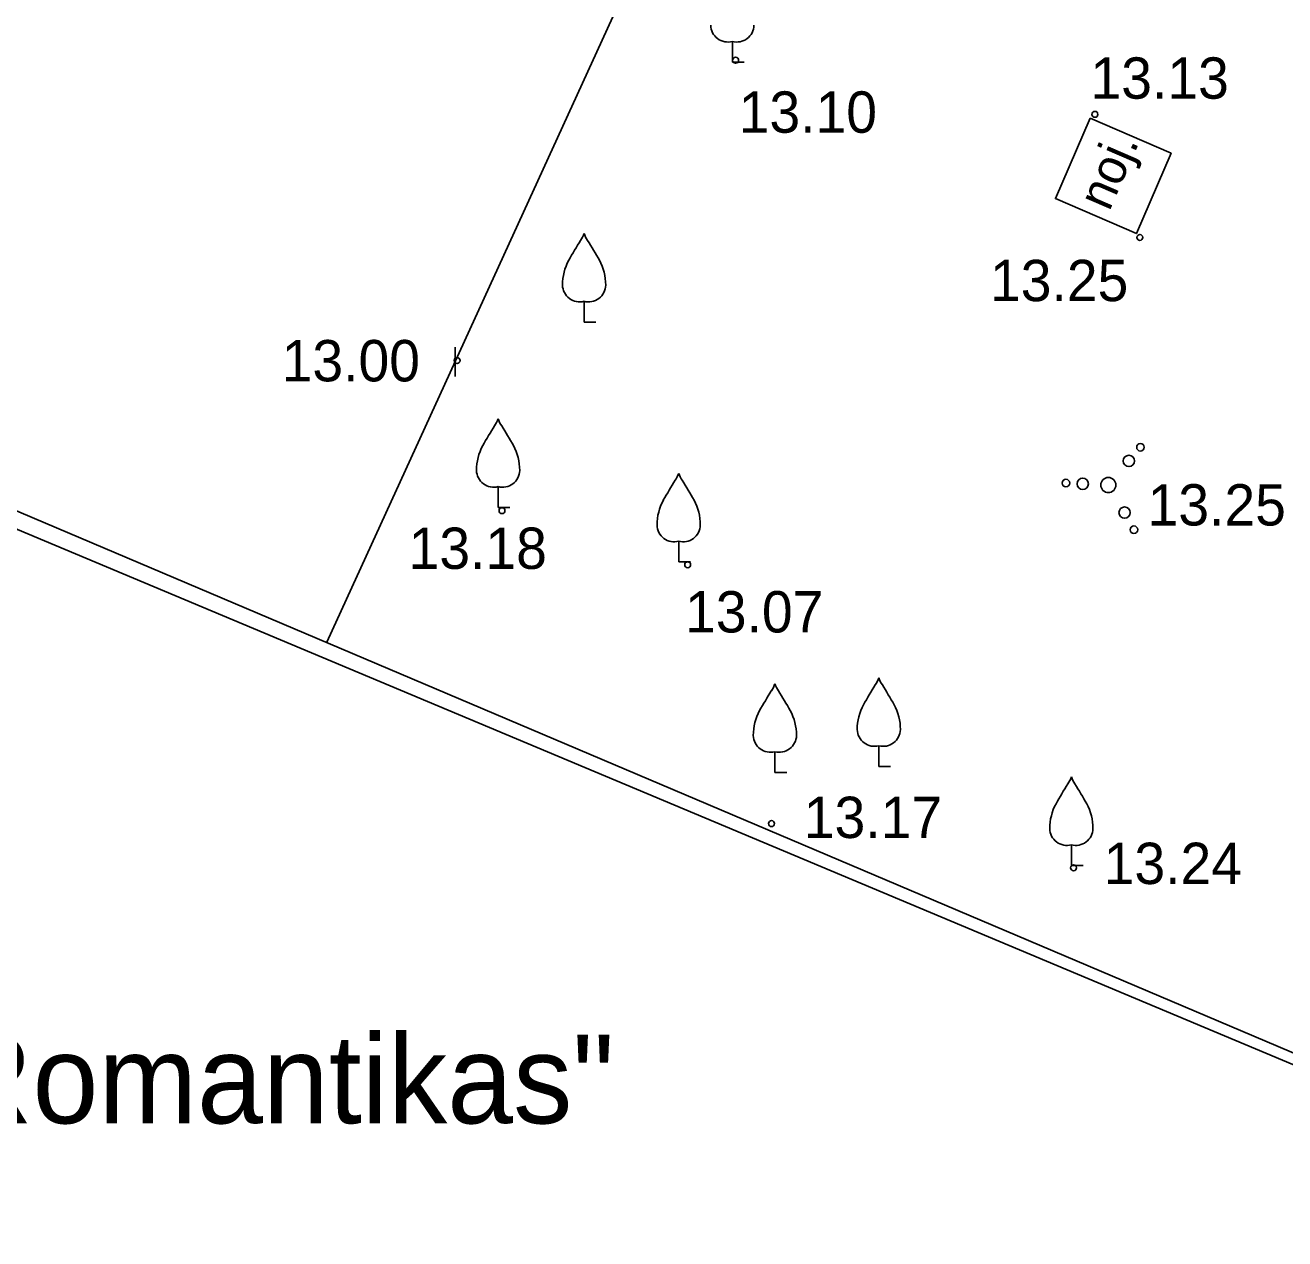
# Model space of a CAD drawing. Extents: x 503877 to 504025, y 304562 to 304725.
# Drawn here: x 503915.75 to 503937.08, y 304685.73 to 304706.29 of the extents above; entities that cross this region are included whole.
import ezdxf

# ---------------------------------------------------------------- set-up
doc = ezdxf.new("R2010")
doc.units = 0
for name, color, linetype in [('24', 7, 'Continuous'), ('BUVE_EKAS_####_####_#', 7, 'Continuous'), ('BUVE_EKAS_ADRS_TKST_#', 7, 'Continuous'), ('Level 1', 7, 'Continuous'), ('NORB_ZOGS_SBST_####_#', 7, 'Continuous'), ('RELJ_AATZ_####_TKST_#', 7, 'Continuous'), ('RELJ_ELEM_####_####_#', 7, 'Continuous'), ('TERT_ELEM_####_####_#', 7, 'Continuous')]:
    doc.layers.add(name, color=color, linetype=linetype)

msp = doc.modelspace()

# ---------------------------------------------------------------- linework, layer by layer
at = {"layer": '24'}
msp.add_line((503908.524, 304700.716), (503951.131, 304682.848), dxfattribs=at)
at = {"layer": 'BUVE_EKAS_####_####_#'}
msp.add_lwpolyline([(503933.782, 304704.71), (503935.154, 304704.117), (503934.566, 304702.756), (503933.194, 304703.349)], close=True, dxfattribs=at)
at = {"layer": 'Level 1'}
msp.add_line((503923.026, 304700.334), (503923.026, 304700.834), dxfattribs=at)
at = {"layer": 'NORB_ZOGS_SBST_####_#'}
for p, q in [((503928.336, 304712.215), (503920.857, 304695.837)), ((503908.544, 304701.057), (503939.387, 304687.964))]:
    msp.add_line(p, q, dxfattribs=at)
at = {"layer": 'RELJ_ELEM_####_####_#'}
for centre in [(503927.778, 304705.691), (503933.863, 304704.775), (503934.624, 304702.691), (503923.061, 304700.606), (503923.822, 304698.064), (503926.966, 304697.149), (503928.387, 304692.765), (503933.502, 304692.017)]:
    msp.add_circle(centre, 0.05, dxfattribs=at)
at = {"layer": 'TERT_ELEM_####_####_#'}
for p, q in [((503927.723, 304706.011), (503927.723, 304705.659)), ((503927.723, 304705.659), (503927.923, 304705.659)), ((503925.212, 304701.611), (503925.212, 304701.259)), ((503925.212, 304701.259), (503925.412, 304701.259)), ((503923.756, 304698.472), (503923.756, 304698.12)), ((503923.756, 304698.12), (503923.956, 304698.12)), ((503926.814, 304697.548), (503926.814, 304697.196)), ((503926.814, 304697.196), (503927.014, 304697.196)), ((503930.203, 304694.085), (503930.203, 304693.733)), ((503928.443, 304693.984), (503928.443, 304693.632)), ((503928.443, 304693.632), (503928.643, 304693.632)), ((503930.203, 304693.733), (503930.403, 304693.733)), ((503933.464, 304692.407), (503933.464, 304692.055)), ((503933.464, 304692.055), (503933.664, 304692.055))]:
    msp.add_line(p, q, dxfattribs=at)
for centre, radius in [((503934.634, 304699.137), 0.064), ((503934.438, 304698.906), 0.096), ((503933.372, 304698.532), 0.064), ((503933.656, 304698.519), 0.096), ((503934.09, 304698.498), 0.128), ((503934.366, 304698.031), 0.096), ((503934.524, 304697.742), 0.064)]:
    msp.add_circle(centre, radius, dxfattribs=at)
for centre, radius, start, end in [((503927.647, 304706.29), 0.29, 181.0782, 285.2823), ((503927.799, 304706.29), 0.29, 254.7177, 358.9218), ((503937.837, 304694.863), 14.88, 148.4844, 149.9901), ((503924.795, 304702.897), 0.439, 324.3837, 341.712), ((503925.629, 304702.897), 0.439, 198.288, 215.6163), ((503912.587, 304694.863), 14.88, 30.0099, 31.5156), ((503925.736, 304701.884), 0.89, 151.757, 179.9138), ((503924.688, 304701.884), 0.89, 0.0862, 28.243), ((503925.136, 304701.89), 0.29, 181.0782, 285.2823), ((503925.288, 304701.89), 0.29, 254.7177, 358.9218), ((503923.339, 304699.758), 0.439, 324.3837, 341.712), ((503924.173, 304699.758), 0.439, 198.288, 215.6163), ((503936.381, 304691.724), 14.88, 148.4844, 149.9901), ((503911.131, 304691.724), 14.88, 30.0099, 31.5156), ((503924.28, 304698.745), 0.89, 151.757, 179.9138), ((503923.232, 304698.745), 0.89, 0.0862, 28.243), ((503923.68, 304698.751), 0.29, 181.0782, 285.2823), ((503923.832, 304698.751), 0.29, 254.7177, 358.9218), ((503939.439, 304690.8), 14.88, 148.4844, 149.9901), ((503926.397, 304698.834), 0.439, 324.3837, 341.712), ((503927.231, 304698.834), 0.439, 198.288, 215.6163), ((503914.189, 304690.8), 14.88, 30.0099, 31.5156), ((503927.338, 304697.821), 0.89, 151.757, 179.9138), ((503926.29, 304697.821), 0.89, 0.0862, 28.243), ((503926.738, 304697.827), 0.29, 181.0782, 285.2823), ((503926.89, 304697.827), 0.29, 254.7177, 358.9218), ((503928.026, 304695.27), 0.439, 324.3837, 341.712), ((503928.86, 304695.27), 0.439, 198.288, 215.6163), ((503942.828, 304687.337), 14.88, 148.4844, 149.9901), ((503929.786, 304695.371), 0.439, 324.3837, 341.712), ((503930.62, 304695.371), 0.439, 198.288, 215.6163), ((503917.578, 304687.337), 14.88, 30.0099, 31.5156), ((503941.068, 304687.236), 14.88, 148.4844, 149.9901), ((503915.818, 304687.236), 14.88, 30.0099, 31.5156), ((503928.967, 304694.257), 0.89, 151.757, 179.9138), ((503927.919, 304694.257), 0.89, 0.0862, 28.243), ((503930.727, 304694.358), 0.89, 151.757, 179.9138), ((503929.679, 304694.358), 0.89, 0.0862, 28.243), ((503928.367, 304694.263), 0.29, 181.0782, 285.2823), ((503928.519, 304694.263), 0.29, 254.7177, 358.9218), ((503930.127, 304694.364), 0.29, 181.0782, 285.2823), ((503930.279, 304694.364), 0.29, 254.7177, 358.9218), ((503946.089, 304685.659), 14.88, 148.4844, 149.9901), ((503933.047, 304693.693), 0.439, 324.3837, 341.712), ((503933.881, 304693.693), 0.439, 198.288, 215.6163), ((503920.839, 304685.659), 14.88, 30.0099, 31.5156), ((503933.988, 304692.68), 0.89, 151.757, 179.9138), ((503932.94, 304692.68), 0.89, 0.0862, 28.243), ((503933.388, 304692.686), 0.29, 181.0782, 285.2823), ((503933.54, 304692.686), 0.29, 254.7177, 358.9218)]:
    msp.add_arc(centre, radius, start, end, dxfattribs=at)

# ---------------------------------------------------------------- texts
at = {"layer": 'BUVE_EKAS_####_####_#'}
msp.add_text('noj.', height=0.6, rotation=66.634, dxfattribs=at).set_placement((503934.106, 304703.119))
at = {"layer": 'BUVE_EKAS_ADRS_TKST_#'}
msp.add_text('a.z. "Romantikas"', height=1.5, dxfattribs=at).set_placement((503909.92, 304687.69))
at = {"layer": 'RELJ_AATZ_####_TKST_#'}
for s, p in [('13.13', (503933.788, 304705.04)), ('13.10', (503927.83, 304704.464)), ('13.25', (503932.086, 304701.612)), ('13.00', (503920.09, 304700.254)), ('13.25', (503934.755, 304697.813)), ('13.18', (503922.24, 304697.078)), ('13.07', (503926.922, 304696.002)), ('13.17', (503928.933, 304692.521)), ('13.24', (503934.011, 304691.742))]:
    msp.add_text(s, height=0.7, dxfattribs=at).set_placement(p)

doc.saveas('drawing.dxf')
